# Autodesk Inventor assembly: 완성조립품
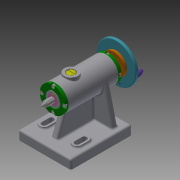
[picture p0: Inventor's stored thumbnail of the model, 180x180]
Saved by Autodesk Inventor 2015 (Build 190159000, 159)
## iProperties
Created: 2022-06
Part Number: 완성조립품
Document SubType Name: Assembly
Designer: 102566
Author: 102566
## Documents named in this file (18)
- C:\Users\102566\Desktop\720606V1015\완성조립품.iam
- C:\Users\102566\Desktop\720606V1015\나사.ipt
- C:\Users\102566\Desktop\720606V1015\나사축.ipt
- C:\Users\102566\Desktop\720606V1015\너트 M8.ipt
- C:\Users\102566\Desktop\720606V1015\돌림판.ipt
- C:\Users\102566\Desktop\720606V1015\멈춤나사 M3.ipt
- C:\Users\102566\Desktop\720606V1015\본체.ipt
- C:\Users\102566\Desktop\720606V1015\볼트 M3.ipt
- C:\Users\102566\Desktop\720606V1015\부시.ipt
- C:\Users\102566\Desktop\720606V1015\센터.ipt
- C:\Users\102566\Desktop\720606V1015\센터홀더.ipt
- C:\Users\102566\Desktop\720606V1015\슬리브.ipt
- C:\Users\102566\Desktop\720606V1015\와셔.ipt
- C:\Users\102566\Desktop\720606V1015\중공축.ipt
- C:\Users\102566\Desktop\720606V1015\커버.ipt
- C:\Users\102566\Desktop\720606V1015\키 4 x 4 x 10.ipt
- C:\Users\102566\Desktop\720606V1015\플랜지.ipt
- C:\Users\102566\Desktop\720606V1015\핸들.ipt
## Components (2 placed, 2 different names)
1. 플랜지:1 — 각도:2
2. 핸들:1 — 플러쉬:1
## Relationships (2: Angle 1, Flush 1)
- 각도:2 [Angle]: 플랜지:1
- 플러쉬:1 [Flush]: 핸들:1
